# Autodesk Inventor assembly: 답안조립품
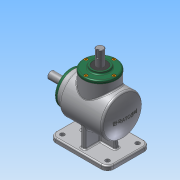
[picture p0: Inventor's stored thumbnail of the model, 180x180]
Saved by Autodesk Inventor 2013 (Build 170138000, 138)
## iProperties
Created: 2016-09
Part Number: 답안조립품
Document SubType Name: Assembly
Designer: Administrator
Author: Administrator
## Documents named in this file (14)
- C:\Users\Administrator\Desktop\460908V1016\답안조립품.iam
- C:\Users\Administrator\Desktop\460908V1016\본체.ipt
- C:\Users\Administrator\Desktop\460908V1016\M4.ipt
- C:\Users\Administrator\Desktop\460908V1016\메인 베벨기어.ipt
- C:\Users\Administrator\Desktop\460908V1016\메인 축.ipt
- 메인 축.ipt
- C:\Users\Administrator\Desktop\460908V1016\베어링 6203.ipt
- C:\Users\Administrator\Desktop\460908V1016\서브 베벨기어.ipt
- C:\Users\Administrator\Desktop\460908V1016\서브 축.ipt
- 서브 축.ipt
- C:\Users\Administrator\Desktop\460908V1016\오일실 17 32 8.ipt
- C:\Users\Administrator\Desktop\460908V1016\커버.ipt
- C:\Users\Administrator\Desktop\460908V1016\키 4x4.ipt
- C:\Users\Administrator\Desktop\460908V1016\키 5x5.ipt
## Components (8 placed, 1 different names)
1. M4:1
2. M4:3
3. M4:4
4. M4:5
5. M4:2
6. M4:6
7. M4:7
8. M4:8
